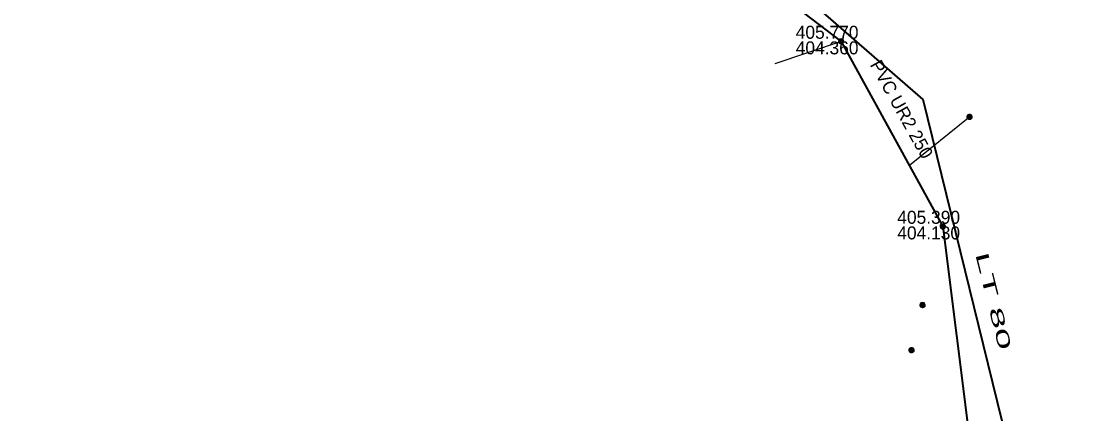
# Model space of a CAD drawing. Extents: x -873619 to -867639, y -1015082 to -1012326.
# Drawn here: x -868171.2 to -868080.5, y -1012809.1 to -1012775.9 of the extents above; entities that cross this region are included whole.
import ezdxf

# ---------------------------------------------------------------- set-up
doc = ezdxf.new("R2010")
doc.units = 0
doc.header["$LTSCALE"] = 0.44
for name, color, linetype, lineweight in [('1', 7, 'Continuous', 13), ('21', 7, 'Continuous', 35), ('23', 7, 'Continuous', 25), ('25', 7, 'Continuous', 13), ('32', 7, 'Continuous', 13)]:
    doc.layers.add(name, color=color, linetype=linetype, lineweight=lineweight)

msp = doc.modelspace()

# ---------------------------------------------------------------- linework, layer by layer
at = {"layer": '1', "lineweight": 35}
for points in [[(-868094.808, -1012782.506), (-868128.65, -1012753.034), (-868142.107, -1012741.315), (-868163.447, -1012723.713), (-868165.629, -1012721.604), (-868186.647, -1012703.368), (-868189.69, -1012700.802), (-868224.291, -1012669.746), (-868245.779, -1012651.034), (-868246.236, -1012651.387)], [(-868085.171, -1012827.86), (-868086.94, -1012814.56), (-868094.808, -1012782.506)]]:
    msp.add_lwpolyline(points, dxfattribs=at)
at = {"layer": '21'}
msp.add_lwpolyline([(-868134.19, -1012752.63), (-868112.27, -1012769.62), (-868107.42, -1012773.25), (-868101.75, -1012777.58), (-868093.15, -1012793.25), (-868087.37, -1012839.18), (-868062.459, -1012846.83), (-868020.28, -1012856.9)], dxfattribs=at)
at = {"layer": '23'}
for p, q in [((-868101.75, -1012777.58), (-868107.36, -1012779.49)), ((-868090.86, -1012783.97), (-868095.977, -1012788.1))]:
    msp.add_line(p, q, dxfattribs=at)
at = {"layer": '25'}
for points in [[(-868095.565, -1012803.726), (-868095.571, -1012803.674), (-868095.588, -1012803.624), (-868095.617, -1012803.58), (-868095.654, -1012803.543), (-868095.699, -1012803.516), (-868095.749, -1012803.499), (-868095.802, -1012803.495), (-868095.853, -1012803.502), (-868095.902, -1012803.521), (-868095.946, -1012803.55), (-868095.982, -1012803.589), (-868096.008, -1012803.634), (-868096.024, -1012803.685), (-868096.027, -1012803.737), (-868096.019, -1012803.789), (-868095.999, -1012803.838), (-868095.968, -1012803.881), (-868095.929, -1012803.915), (-868095.883, -1012803.941), (-868095.831, -1012803.955), (-868095.779, -1012803.957), (-868095.728, -1012803.947), (-868095.679, -1012803.926), (-868095.637, -1012803.895), (-868095.603, -1012803.854), (-868095.579, -1012803.808), (-868095.566, -1012803.757)], [(-868095.595, -1012803.726), (-868095.601, -1012803.677), (-868095.618, -1012803.631), (-868095.646, -1012803.591), (-868095.683, -1012803.559), (-868095.727, -1012803.537), (-868095.775, -1012803.526), (-868095.824, -1012803.526), (-868095.87, -1012803.539), (-868095.914, -1012803.563), (-868095.95, -1012803.596), (-868095.977, -1012803.637), (-868095.993, -1012803.684), (-868095.997, -1012803.733), (-868095.99, -1012803.781), (-868095.971, -1012803.826), (-868095.941, -1012803.866), (-868095.902, -1012803.897), (-868095.858, -1012803.917), (-868095.811, -1012803.927), (-868095.762, -1012803.925), (-868095.715, -1012803.91), (-868095.672, -1012803.885), (-868095.637, -1012803.851), (-868095.612, -1012803.809), (-868095.598, -1012803.762)], [(-868095.625, -1012803.726), (-868095.63, -1012803.681), (-868095.647, -1012803.639), (-868095.676, -1012803.604), (-868095.712, -1012803.577), (-868095.754, -1012803.56), (-868095.799, -1012803.555), (-868095.843, -1012803.561), (-868095.885, -1012803.58), (-868095.919, -1012803.608), (-868095.946, -1012803.645), (-868095.963, -1012803.687), (-868095.967, -1012803.732), (-868095.96, -1012803.777), (-868095.941, -1012803.818), (-868095.912, -1012803.852), (-868095.875, -1012803.878), (-868095.831, -1012803.894), (-868095.787, -1012803.897), (-868095.742, -1012803.889), (-868095.701, -1012803.869), (-868095.668, -1012803.84), (-868095.642, -1012803.802), (-868095.628, -1012803.759)], [(-868095.655, -1012803.726), (-868095.659, -1012803.685), (-868095.678, -1012803.648), (-868095.705, -1012803.617), (-868095.74, -1012803.596), (-868095.78, -1012803.585), (-868095.821, -1012803.587), (-868095.86, -1012803.6), (-868095.894, -1012803.624), (-868095.919, -1012803.656), (-868095.934, -1012803.694), (-868095.936, -1012803.735), (-868095.929, -1012803.775), (-868095.909, -1012803.811), (-868095.88, -1012803.84), (-868095.843, -1012803.859), (-868095.803, -1012803.867), (-868095.762, -1012803.863), (-868095.723, -1012803.848), (-868095.691, -1012803.822), (-868095.669, -1012803.788), (-868095.656, -1012803.749)], [(-868095.684, -1012803.726), (-868095.69, -1012803.69), (-868095.708, -1012803.658), (-868095.733, -1012803.633), (-868095.767, -1012803.618), (-868095.804, -1012803.615), (-868095.838, -1012803.623), (-868095.87, -1012803.643), (-868095.892, -1012803.671), (-868095.906, -1012803.705), (-868095.906, -1012803.742), (-868095.895, -1012803.777), (-868095.874, -1012803.806), (-868095.843, -1012803.827), (-868095.809, -1012803.837), (-868095.772, -1012803.835), (-868095.738, -1012803.821), (-868095.711, -1012803.798), (-868095.691, -1012803.766), (-868095.684, -1012803.731)], [(-868095.715, -1012803.726), (-868095.72, -1012803.695), (-868095.737, -1012803.669), (-868095.762, -1012803.652), (-868095.793, -1012803.645), (-868095.824, -1012803.649), (-868095.851, -1012803.666), (-868095.869, -1012803.69), (-868095.877, -1012803.721), (-868095.873, -1012803.751), (-868095.858, -1012803.779), (-868095.833, -1012803.798), (-868095.804, -1012803.807), (-868095.772, -1012803.804), (-868095.745, -1012803.79), (-868095.725, -1012803.766), (-868095.715, -1012803.737)], [(-868095.745, -1012803.726), (-868095.75, -1012803.702), (-868095.767, -1012803.684), (-868095.789, -1012803.675), (-868095.814, -1012803.678), (-868095.835, -1012803.692), (-868095.846, -1012803.714), (-868095.846, -1012803.739), (-868095.833, -1012803.76), (-868095.814, -1012803.774), (-868095.789, -1012803.777), (-868095.766, -1012803.768), (-868095.75, -1012803.75)], [(-868095.775, -1012803.726), (-868095.78, -1012803.711), (-868095.794, -1012803.705), (-868095.809, -1012803.709), (-868095.816, -1012803.723), (-868095.813, -1012803.738), (-868095.799, -1012803.747), (-868095.784, -1012803.744), (-868095.775, -1012803.732)]]:
    msp.add_lwpolyline(points, close=True, dxfattribs=at)
at = {"layer": '32'}
for points in [[(-868101.52, -1012777.579), (-868101.526, -1012777.527), (-868101.543, -1012777.477), (-868101.572, -1012777.433), (-868101.609, -1012777.396), (-868101.654, -1012777.369), (-868101.704, -1012777.352), (-868101.757, -1012777.348), (-868101.809, -1012777.355), (-868101.858, -1012777.374), (-868101.901, -1012777.403), (-868101.937, -1012777.442), (-868101.963, -1012777.487), (-868101.979, -1012777.538), (-868101.982, -1012777.59), (-868101.974, -1012777.642), (-868101.954, -1012777.691), (-868101.923, -1012777.734), (-868101.884, -1012777.768), (-868101.838, -1012777.794), (-868101.787, -1012777.808), (-868101.734, -1012777.81), (-868101.683, -1012777.8), (-868101.635, -1012777.779), (-868101.592, -1012777.748), (-868101.558, -1012777.707), (-868101.534, -1012777.661), (-868101.522, -1012777.61)], [(-868101.55, -1012777.579), (-868101.556, -1012777.53), (-868101.573, -1012777.484), (-868101.601, -1012777.444), (-868101.638, -1012777.412), (-868101.682, -1012777.39), (-868101.73, -1012777.379), (-868101.779, -1012777.379), (-868101.826, -1012777.392), (-868101.869, -1012777.416), (-868101.905, -1012777.449), (-868101.932, -1012777.49), (-868101.948, -1012777.537), (-868101.952, -1012777.586), (-868101.945, -1012777.634), (-868101.926, -1012777.679), (-868101.896, -1012777.719), (-868101.858, -1012777.75), (-868101.814, -1012777.77), (-868101.766, -1012777.78), (-868101.717, -1012777.778), (-868101.67, -1012777.763), (-868101.627, -1012777.738), (-868101.593, -1012777.704), (-868101.567, -1012777.662), (-868101.553, -1012777.615)], [(-868101.58, -1012777.579), (-868101.586, -1012777.534), (-868101.603, -1012777.492), (-868101.631, -1012777.457), (-868101.667, -1012777.43), (-868101.709, -1012777.413), (-868101.754, -1012777.408), (-868101.799, -1012777.414), (-868101.84, -1012777.433), (-868101.875, -1012777.461), (-868101.902, -1012777.498), (-868101.918, -1012777.54), (-868101.922, -1012777.585), (-868101.915, -1012777.63), (-868101.896, -1012777.671), (-868101.867, -1012777.705), (-868101.83, -1012777.731), (-868101.787, -1012777.747), (-868101.742, -1012777.75), (-868101.697, -1012777.742), (-868101.657, -1012777.722), (-868101.623, -1012777.693), (-868101.597, -1012777.655), (-868101.583, -1012777.612)], [(-868101.61, -1012777.579), (-868101.615, -1012777.538), (-868101.633, -1012777.501), (-868101.66, -1012777.47), (-868101.695, -1012777.449), (-868101.735, -1012777.438), (-868101.776, -1012777.44), (-868101.815, -1012777.453), (-868101.849, -1012777.477), (-868101.874, -1012777.509), (-868101.889, -1012777.547), (-868101.892, -1012777.588), (-868101.884, -1012777.628), (-868101.864, -1012777.664), (-868101.835, -1012777.693), (-868101.798, -1012777.712), (-868101.758, -1012777.72), (-868101.717, -1012777.716), (-868101.679, -1012777.701), (-868101.647, -1012777.675), (-868101.624, -1012777.641), (-868101.611, -1012777.602)], [(-868101.64, -1012777.579), (-868101.645, -1012777.543), (-868101.663, -1012777.511), (-868101.689, -1012777.486), (-868101.723, -1012777.471), (-868101.759, -1012777.468), (-868101.794, -1012777.476), (-868101.825, -1012777.496), (-868101.848, -1012777.524), (-868101.861, -1012777.558), (-868101.861, -1012777.595), (-868101.85, -1012777.63), (-868101.829, -1012777.659), (-868101.799, -1012777.68), (-868101.764, -1012777.69), (-868101.727, -1012777.688), (-868101.693, -1012777.674), (-868101.666, -1012777.651), (-868101.647, -1012777.619), (-868101.64, -1012777.584)], [(-868101.67, -1012777.579), (-868101.675, -1012777.548), (-868101.692, -1012777.522), (-868101.718, -1012777.505), (-868101.748, -1012777.498), (-868101.779, -1012777.502), (-868101.806, -1012777.519), (-868101.824, -1012777.543), (-868101.832, -1012777.574), (-868101.828, -1012777.604), (-868101.813, -1012777.632), (-868101.789, -1012777.651), (-868101.759, -1012777.66), (-868101.728, -1012777.657), (-868101.7, -1012777.643), (-868101.68, -1012777.619), (-868101.67, -1012777.59)], [(-868101.7, -1012777.579), (-868101.705, -1012777.555), (-868101.722, -1012777.537), (-868101.745, -1012777.528), (-868101.769, -1012777.531), (-868101.79, -1012777.545), (-868101.801, -1012777.567), (-868101.801, -1012777.592), (-868101.789, -1012777.613), (-868101.769, -1012777.627), (-868101.744, -1012777.63), (-868101.721, -1012777.621), (-868101.705, -1012777.603)], [(-868101.73, -1012777.579), (-868101.735, -1012777.564), (-868101.75, -1012777.558), (-868101.765, -1012777.562), (-868101.772, -1012777.576), (-868101.768, -1012777.591), (-868101.755, -1012777.6), (-868101.74, -1012777.597), (-868101.73, -1012777.585)], [(-868090.65, -1012783.969), (-868090.656, -1012783.917), (-868090.673, -1012783.867), (-868090.702, -1012783.823), (-868090.739, -1012783.786), (-868090.784, -1012783.759), (-868090.834, -1012783.742), (-868090.887, -1012783.738), (-868090.939, -1012783.745), (-868090.988, -1012783.764), (-868091.031, -1012783.793), (-868091.067, -1012783.832), (-868091.093, -1012783.877), (-868091.109, -1012783.928), (-868091.112, -1012783.98), (-868091.104, -1012784.032), (-868091.084, -1012784.081), (-868091.053, -1012784.124), (-868091.014, -1012784.158), (-868090.968, -1012784.184), (-868090.917, -1012784.198), (-868090.864, -1012784.2), (-868090.813, -1012784.19), (-868090.765, -1012784.169), (-868090.722, -1012784.138), (-868090.688, -1012784.097), (-868090.664, -1012784.051), (-868090.652, -1012784)], [(-868090.68, -1012783.969), (-868090.686, -1012783.92), (-868090.703, -1012783.874), (-868090.731, -1012783.834), (-868090.768, -1012783.802), (-868090.812, -1012783.78), (-868090.86, -1012783.769), (-868090.909, -1012783.769), (-868090.956, -1012783.782), (-868090.999, -1012783.806), (-868091.035, -1012783.839), (-868091.062, -1012783.88), (-868091.078, -1012783.927), (-868091.082, -1012783.976), (-868091.075, -1012784.024), (-868091.056, -1012784.069), (-868091.026, -1012784.109), (-868090.988, -1012784.14), (-868090.944, -1012784.16), (-868090.896, -1012784.17), (-868090.847, -1012784.168), (-868090.8, -1012784.153), (-868090.757, -1012784.128), (-868090.723, -1012784.094), (-868090.697, -1012784.052), (-868090.683, -1012784.005)], [(-868090.71, -1012783.969), (-868090.716, -1012783.924), (-868090.733, -1012783.882), (-868090.761, -1012783.847), (-868090.797, -1012783.82), (-868090.839, -1012783.803), (-868090.884, -1012783.798), (-868090.929, -1012783.804), (-868090.97, -1012783.823), (-868091.005, -1012783.851), (-868091.032, -1012783.888), (-868091.048, -1012783.93), (-868091.052, -1012783.975), (-868091.045, -1012784.02), (-868091.026, -1012784.061), (-868090.997, -1012784.095), (-868090.96, -1012784.121), (-868090.917, -1012784.137), (-868090.872, -1012784.14), (-868090.827, -1012784.132), (-868090.787, -1012784.112), (-868090.753, -1012784.083), (-868090.727, -1012784.045), (-868090.713, -1012784.002)], [(-868090.74, -1012783.969), (-868090.745, -1012783.928), (-868090.763, -1012783.891), (-868090.79, -1012783.86), (-868090.825, -1012783.839), (-868090.865, -1012783.828), (-868090.906, -1012783.83), (-868090.945, -1012783.843), (-868090.979, -1012783.867), (-868091.004, -1012783.899), (-868091.019, -1012783.937), (-868091.022, -1012783.978), (-868091.014, -1012784.018), (-868090.994, -1012784.054), (-868090.965, -1012784.083), (-868090.928, -1012784.102), (-868090.888, -1012784.11), (-868090.847, -1012784.106), (-868090.809, -1012784.091), (-868090.777, -1012784.065), (-868090.754, -1012784.031), (-868090.741, -1012783.992)], [(-868090.77, -1012783.969), (-868090.775, -1012783.933), (-868090.793, -1012783.901), (-868090.819, -1012783.876), (-868090.853, -1012783.861), (-868090.889, -1012783.858), (-868090.924, -1012783.866), (-868090.955, -1012783.886), (-868090.978, -1012783.914), (-868090.991, -1012783.948), (-868090.991, -1012783.985), (-868090.98, -1012784.02), (-868090.959, -1012784.049), (-868090.929, -1012784.07), (-868090.894, -1012784.08), (-868090.857, -1012784.078), (-868090.823, -1012784.064), (-868090.796, -1012784.041), (-868090.777, -1012784.009), (-868090.77, -1012783.974)], [(-868090.8, -1012783.969), (-868090.805, -1012783.938), (-868090.822, -1012783.912), (-868090.848, -1012783.895), (-868090.878, -1012783.888), (-868090.909, -1012783.892), (-868090.936, -1012783.909), (-868090.954, -1012783.933), (-868090.962, -1012783.964), (-868090.958, -1012783.994), (-868090.943, -1012784.022), (-868090.919, -1012784.041), (-868090.889, -1012784.05), (-868090.858, -1012784.047), (-868090.83, -1012784.033), (-868090.81, -1012784.009), (-868090.8, -1012783.98)], [(-868090.83, -1012783.969), (-868090.835, -1012783.945), (-868090.852, -1012783.927), (-868090.875, -1012783.918), (-868090.899, -1012783.921), (-868090.92, -1012783.935), (-868090.931, -1012783.957), (-868090.931, -1012783.982), (-868090.919, -1012784.003), (-868090.899, -1012784.017), (-868090.874, -1012784.02), (-868090.851, -1012784.011), (-868090.835, -1012783.993)], [(-868090.86, -1012783.969), (-868090.865, -1012783.954), (-868090.88, -1012783.948), (-868090.895, -1012783.952), (-868090.902, -1012783.966), (-868090.898, -1012783.981), (-868090.885, -1012783.99), (-868090.87, -1012783.987), (-868090.86, -1012783.975)], [(-868092.919, -1012793.249), (-868092.926, -1012793.197), (-868092.943, -1012793.147), (-868092.972, -1012793.103), (-868093.009, -1012793.066), (-868093.054, -1012793.039), (-868093.103, -1012793.022), (-868093.157, -1012793.018), (-868093.208, -1012793.025), (-868093.257, -1012793.044), (-868093.301, -1012793.073), (-868093.337, -1012793.112), (-868093.363, -1012793.157), (-868093.379, -1012793.208), (-868093.382, -1012793.26), (-868093.374, -1012793.312), (-868093.353, -1012793.361), (-868093.323, -1012793.404), (-868093.284, -1012793.438), (-868093.238, -1012793.464), (-868093.186, -1012793.478), (-868093.134, -1012793.48), (-868093.083, -1012793.47), (-868093.034, -1012793.449), (-868092.992, -1012793.418), (-868092.958, -1012793.377), (-868092.934, -1012793.331), (-868092.921, -1012793.28)], [(-868092.95, -1012793.249), (-868092.956, -1012793.2), (-868092.973, -1012793.154), (-868093, -1012793.114), (-868093.038, -1012793.082), (-868093.081, -1012793.06), (-868093.13, -1012793.049), (-868093.179, -1012793.049), (-868093.225, -1012793.062), (-868093.269, -1012793.086), (-868093.304, -1012793.119), (-868093.331, -1012793.16), (-868093.348, -1012793.207), (-868093.352, -1012793.256), (-868093.345, -1012793.304), (-868093.326, -1012793.349), (-868093.296, -1012793.389), (-868093.257, -1012793.42), (-868093.213, -1012793.44), (-868093.166, -1012793.45), (-868093.117, -1012793.448), (-868093.07, -1012793.433), (-868093.027, -1012793.408), (-868092.992, -1012793.374), (-868092.967, -1012793.332), (-868092.953, -1012793.285)], [(-868092.98, -1012793.249), (-868092.985, -1012793.204), (-868093.002, -1012793.162), (-868093.031, -1012793.127), (-868093.066, -1012793.1), (-868093.108, -1012793.083), (-868093.154, -1012793.078), (-868093.198, -1012793.084), (-868093.24, -1012793.103), (-868093.274, -1012793.131), (-868093.301, -1012793.168), (-868093.318, -1012793.21), (-868093.321, -1012793.255), (-868093.315, -1012793.3), (-868093.296, -1012793.341), (-868093.267, -1012793.375), (-868093.23, -1012793.401), (-868093.186, -1012793.417), (-868093.142, -1012793.42), (-868093.097, -1012793.412), (-868093.056, -1012793.392), (-868093.022, -1012793.363), (-868092.997, -1012793.325), (-868092.983, -1012793.282)], [(-868093.01, -1012793.249), (-868093.014, -1012793.208), (-868093.032, -1012793.171), (-868093.059, -1012793.14), (-868093.095, -1012793.119), (-868093.135, -1012793.108), (-868093.176, -1012793.11), (-868093.215, -1012793.123), (-868093.249, -1012793.147), (-868093.274, -1012793.179), (-868093.289, -1012793.217), (-868093.291, -1012793.258), (-868093.284, -1012793.298), (-868093.264, -1012793.334), (-868093.235, -1012793.363), (-868093.198, -1012793.382), (-868093.157, -1012793.39), (-868093.117, -1012793.386), (-868093.078, -1012793.371), (-868093.046, -1012793.345), (-868093.024, -1012793.311), (-868093.011, -1012793.272)], [(-868093.039, -1012793.249), (-868093.044, -1012793.213), (-868093.063, -1012793.181), (-868093.088, -1012793.156), (-868093.122, -1012793.141), (-868093.159, -1012793.138), (-868093.193, -1012793.146), (-868093.225, -1012793.166), (-868093.247, -1012793.194), (-868093.261, -1012793.228), (-868093.261, -1012793.265), (-868093.25, -1012793.3), (-868093.228, -1012793.329), (-868093.198, -1012793.35), (-868093.164, -1012793.36), (-868093.127, -1012793.358), (-868093.093, -1012793.344), (-868093.066, -1012793.321), (-868093.046, -1012793.289), (-868093.039, -1012793.254)], [(-868093.07, -1012793.249), (-868093.075, -1012793.218), (-868093.092, -1012793.192), (-868093.117, -1012793.175), (-868093.147, -1012793.168), (-868093.179, -1012793.172), (-868093.206, -1012793.189), (-868093.223, -1012793.213), (-868093.232, -1012793.244), (-868093.228, -1012793.274), (-868093.213, -1012793.302), (-868093.188, -1012793.321), (-868093.159, -1012793.33), (-868093.127, -1012793.327), (-868093.1, -1012793.313), (-868093.08, -1012793.289), (-868093.07, -1012793.26)], [(-868093.1, -1012793.249), (-868093.105, -1012793.225), (-868093.122, -1012793.207), (-868093.144, -1012793.198), (-868093.169, -1012793.201), (-868093.19, -1012793.215), (-868093.201, -1012793.237), (-868093.201, -1012793.262), (-868093.188, -1012793.283), (-868093.169, -1012793.297), (-868093.144, -1012793.3), (-868093.12, -1012793.291), (-868093.105, -1012793.273)], [(-868093.13, -1012793.249), (-868093.135, -1012793.234), (-868093.149, -1012793.228), (-868093.164, -1012793.232), (-868093.171, -1012793.246), (-868093.168, -1012793.261), (-868093.154, -1012793.27), (-868093.139, -1012793.267), (-868093.13, -1012793.255)], [(-868094.63, -1012799.909), (-868094.636, -1012799.857), (-868094.653, -1012799.807), (-868094.682, -1012799.763), (-868094.719, -1012799.726), (-868094.764, -1012799.699), (-868094.814, -1012799.682), (-868094.867, -1012799.678), (-868094.919, -1012799.685), (-868094.968, -1012799.704), (-868095.011, -1012799.733), (-868095.047, -1012799.772), (-868095.073, -1012799.817), (-868095.089, -1012799.868), (-868095.092, -1012799.92), (-868095.084, -1012799.972), (-868095.064, -1012800.021), (-868095.033, -1012800.064), (-868094.994, -1012800.098), (-868094.948, -1012800.124), (-868094.897, -1012800.138), (-868094.844, -1012800.14), (-868094.793, -1012800.13), (-868094.745, -1012800.109), (-868094.702, -1012800.078), (-868094.668, -1012800.037), (-868094.644, -1012799.991), (-868094.632, -1012799.94)], [(-868094.66, -1012799.909), (-868094.666, -1012799.86), (-868094.683, -1012799.814), (-868094.711, -1012799.774), (-868094.748, -1012799.742), (-868094.792, -1012799.72), (-868094.84, -1012799.709), (-868094.889, -1012799.709), (-868094.936, -1012799.722), (-868094.979, -1012799.746), (-868095.015, -1012799.779), (-868095.042, -1012799.82), (-868095.058, -1012799.867), (-868095.062, -1012799.916), (-868095.055, -1012799.964), (-868095.036, -1012800.009), (-868095.006, -1012800.049), (-868094.968, -1012800.08), (-868094.924, -1012800.1), (-868094.876, -1012800.11), (-868094.827, -1012800.108), (-868094.78, -1012800.093), (-868094.737, -1012800.068), (-868094.703, -1012800.034), (-868094.677, -1012799.992), (-868094.663, -1012799.945)], [(-868094.69, -1012799.909), (-868094.696, -1012799.864), (-868094.713, -1012799.822), (-868094.741, -1012799.787), (-868094.777, -1012799.76), (-868094.819, -1012799.743), (-868094.864, -1012799.738), (-868094.909, -1012799.744), (-868094.95, -1012799.763), (-868094.985, -1012799.791), (-868095.012, -1012799.828), (-868095.028, -1012799.87), (-868095.032, -1012799.915), (-868095.025, -1012799.96), (-868095.006, -1012800.001), (-868094.977, -1012800.035), (-868094.94, -1012800.061), (-868094.897, -1012800.077), (-868094.852, -1012800.08), (-868094.807, -1012800.072), (-868094.767, -1012800.052), (-868094.733, -1012800.023), (-868094.707, -1012799.985), (-868094.693, -1012799.942)], [(-868094.72, -1012799.909), (-868094.725, -1012799.868), (-868094.743, -1012799.831), (-868094.77, -1012799.8), (-868094.805, -1012799.779), (-868094.845, -1012799.768), (-868094.886, -1012799.77), (-868094.925, -1012799.783), (-868094.959, -1012799.807), (-868094.984, -1012799.839), (-868094.999, -1012799.877), (-868095.002, -1012799.918), (-868094.994, -1012799.958), (-868094.974, -1012799.994), (-868094.945, -1012800.023), (-868094.908, -1012800.042), (-868094.868, -1012800.05), (-868094.827, -1012800.046), (-868094.789, -1012800.031), (-868094.757, -1012800.005), (-868094.734, -1012799.971), (-868094.721, -1012799.932)], [(-868094.75, -1012799.909), (-868094.755, -1012799.873), (-868094.773, -1012799.841), (-868094.799, -1012799.816), (-868094.833, -1012799.801), (-868094.869, -1012799.798), (-868094.904, -1012799.806), (-868094.935, -1012799.826), (-868094.958, -1012799.854), (-868094.971, -1012799.888), (-868094.971, -1012799.925), (-868094.96, -1012799.96), (-868094.939, -1012799.989), (-868094.909, -1012800.01), (-868094.874, -1012800.02), (-868094.837, -1012800.018), (-868094.803, -1012800.004), (-868094.776, -1012799.981), (-868094.757, -1012799.949), (-868094.75, -1012799.914)], [(-868094.78, -1012799.909), (-868094.785, -1012799.878), (-868094.802, -1012799.852), (-868094.828, -1012799.835), (-868094.858, -1012799.828), (-868094.889, -1012799.832), (-868094.916, -1012799.849), (-868094.934, -1012799.873), (-868094.942, -1012799.904), (-868094.938, -1012799.934), (-868094.923, -1012799.962), (-868094.899, -1012799.981), (-868094.869, -1012799.99), (-868094.838, -1012799.987), (-868094.81, -1012799.973), (-868094.79, -1012799.949), (-868094.78, -1012799.92)], [(-868094.81, -1012799.909), (-868094.815, -1012799.885), (-868094.832, -1012799.867), (-868094.855, -1012799.858), (-868094.879, -1012799.861), (-868094.9, -1012799.875), (-868094.911, -1012799.897), (-868094.911, -1012799.922), (-868094.899, -1012799.943), (-868094.879, -1012799.957), (-868094.854, -1012799.96), (-868094.831, -1012799.951), (-868094.815, -1012799.933)], [(-868094.84, -1012799.909), (-868094.845, -1012799.894), (-868094.86, -1012799.888), (-868094.875, -1012799.892), (-868094.882, -1012799.906), (-868094.878, -1012799.921), (-868094.865, -1012799.93), (-868094.85, -1012799.927), (-868094.84, -1012799.915)]]:
    msp.add_lwpolyline(points, close=True, dxfattribs=at)

# ---------------------------------------------------------------- texts
at = {"layer": '1'}
for s, p in [('405.770 ', (-868105.601, -1012777.359)), ('404.360 ', (-868105.601, -1012778.679)), ('405.390 ', (-868097.001, -1012793.029)), ('404.130 ', (-868097.001, -1012794.349))]:
    msp.add_text(s, height=1.1, dxfattribs=at).set_placement(p)
msp.add_text('PVC UR2 250 ', height=1.1, rotation=299, dxfattribs=at).set_placement((-868099.351, -1012779.557))
at = {"layer": '1', "width": 2.25}
msp.add_text('LT 80 ', height=1.1, rotation=284, dxfattribs=at).set_placement((-868090.412, -1012795.587))

doc.saveas('drawing.dxf')
